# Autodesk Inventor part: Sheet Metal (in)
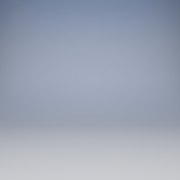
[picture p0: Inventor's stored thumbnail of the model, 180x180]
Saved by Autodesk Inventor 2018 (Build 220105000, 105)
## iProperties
Created: 2017-02
Part Number: Sheet Metal (in)
Material: Ogólny
Document SubType Name: Konstrukcja blachowa
Density: 1 g/cm^3
Appearance: Domyślna
Sheet Metal Rule: Domyślny
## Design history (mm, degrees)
other parameters: "Grubość" = 3.048 (derived), "WspółczynnikK" = 4.4, "PromieńGięcia" = 3.048 (= Grubość), "SzerokośćGięciaPodcięcia" = 3.048 (= Grubość), "GłębokośćGięciaPodcięcia" = 1.524 (= 0.5 x Grubość), "RozmiarPodcięciaNarożnika" = 12.192 (= 4 x Grubość), "OdstępPołączenia" = 0.00508, "MinimalnaPozostałość" = 6.096 (= 2 x Grubość), "PromieńPrzejścia" = 3.048 (= PromieńGięcia), "Rozmiar_promienia_Jacobiego" = 3.048 (= PromieńGięcia), "Wielk_odstępu" = 3.048 (= Grubość)
